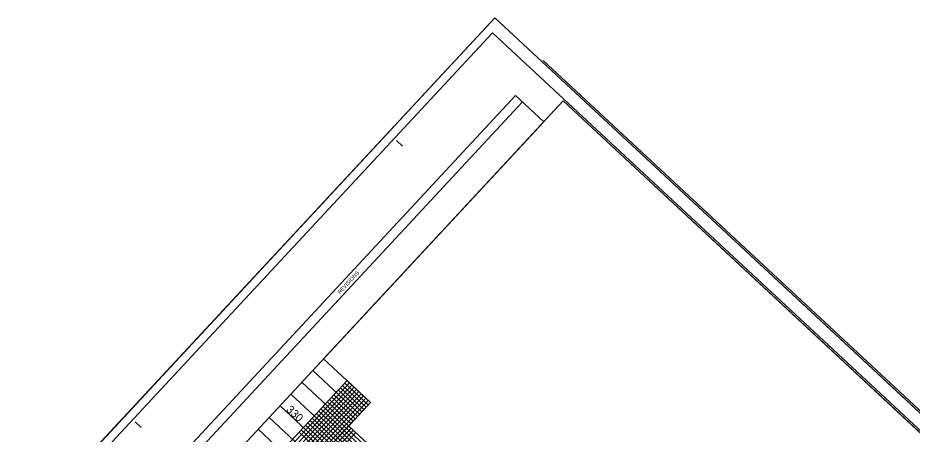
# Model space of a CAD drawing. Extents: x 2057696 to 2061410, y 685900 to 689434.
# Drawn here: x 2057696 to 2058814, y 688913 to 689434 of the extents above; entities that cross this region are included whole.
import ezdxf

# ---------------------------------------------------------------- set-up
doc = ezdxf.new("R2010")
doc.units = 0
for name, color, linetype in [('Default', 7, 'Continuous'), ('Exist Vertical Profile Vertical Axis Label', 7, 'Continuous'), ('Prop Boundary Buffer Zone 2', 7, 'Continuous'), ('Prop Vertical Profile Curve Label', 7, 'Continuous'), ('Sheet Cutting Line CELL', 7, 'Continuous'), ('Sheet Plan CELL', 7, 'Continuous'), ('Sheet Plot Border Inside CELL', 7, 'Continuous')]:
    doc.layers.add(name, color=color, linetype=linetype)

msp = doc.modelspace()

# ---------------------------------------------------------------- linework, layer by layer
at = {"layer": 'Default'}
for p, q in [((2058292.7, 689433.5), (2057696.3, 688791.9)), ((2059279.2, 688516.6), (2058292.7, 689433.5)), ((2059279, 688519.5), (2058353.1, 689380.2)), ((2057806.1, 688714.4), (2058378, 689329.7)), ((2057896.3, 688865.4), (2058326.9, 689328.7)), ((2059257, 688512.7), (2058378, 689329.7)), ((2058169.8, 689280.2), (2058177.1, 689273.4)), ((2058107.8, 688980.2), (2057849.1, 688701.8)), ((2058122.4, 688966.5), (2057863.7, 688688.2)), ((2058122.4, 688966.5), (2058137.1, 688952.9)), ((2057843, 688928.6), (2057850.4, 688921.8)), ((2058109.8, 688923.6), (2057878.4, 688674.6))]:
    msp.add_line(p, q, dxfattribs=at)
for points in [[(2057696.3, 688791.9), (2058682.8, 687875), (2059279.2, 688516.6), (2058292.7, 689433.5)], [(2057714.8, 688796.5), (2058691.1, 687889.2), (2059265.7, 688507.4), (2058289.4, 689414.7)], [(2057887.8, 688873.4), (2058318.4, 689336.7), (2058353.9, 689303.7), (2057923.2, 688840.4)]]:
    msp.add_lwpolyline(points, close=True, dxfattribs=at)
at = {"layer": 'Exist Vertical Profile Vertical Axis Label'}
for points in [[(2057852, 688699.1), (2058110.7, 688977.4), (2058113.6, 688974.7), (2057854.9, 688696.4)], [(2057857.9, 688693.6), (2058116.6, 688972), (2058119.5, 688969.3), (2057860.8, 688690.9)], [(2057866.6, 688685.5), (2058125.3, 688963.8), (2058128.3, 688961.1), (2057869.6, 688682.8)], [(2057872.5, 688680), (2058131.2, 688958.4), (2058134.1, 688955.6), (2057875.4, 688677.3)], [(2057881.3, 688671.9), (2058112.8, 688920.9)], [(2058115.7, 688918.2), (2057884.2, 688669.1)], [(2057887.2, 688666.4), (2058118.6, 688915.5)]]:
    msp.add_lwpolyline(points, dxfattribs=at)
at = {"layer": 'Prop Boundary Buffer Zone 2'}
for p, q in [((2058123.5, 688938.3), (2058064.9, 688992.7)), ((2057849.1, 688701.8), (2058107.8, 688980.2)), ((2058107.8, 688980.2), (2058137.1, 688952.9)), ((2057863.7, 688688.2), (2058122.4, 688966.5)), ((2058860.5, 688198.6), (2058037.6, 688963.4)), ((2058137.1, 688952.9), (2057878.4, 688674.6)), ((2058833.2, 688169.3), (2058010.4, 688934.1))]:
    msp.add_line(p, q, dxfattribs=at)
at = {"layer": 'Prop Vertical Profile Curve Label'}
for points in [[(2058210.3, 688884.8), (2058901.3, 688242.6), (2059147.2, 688507.2), (2059089, 688561.3), (2059142.6, 688619), (2058378, 689329.7), (2058078.5, 689007.4), (2058137.1, 688952.9)], [(2058137.1, 688952.9), (2058107.8, 688980.2), (2057849.1, 688701.8), (2058611.6, 687993), (2058870.3, 688271.4), (2058210.3, 688884.8)], [(2058210.3, 688884.8), (2058183.1, 688855.5), (2058109.8, 688923.6), (2058137.1, 688952.9)], [(2058137.1, 688952.9), (2058109.8, 688923.6), (2058183.1, 688855.5), (2058210.3, 688884.8)]]:
    msp.add_lwpolyline(points, dxfattribs=at)
at = {"layer": 'Sheet Cutting Line CELL'}
for p, q in [((2058137.1, 688952.9), (2058078.5, 689007.4)), ((2057849.1, 688701.8), (2058107.8, 688980.2)), ((2058109.8, 688923.6), (2058051.2, 688978.1)), ((2058846.8, 688184), (2058024, 688948.8)), ((2058874.1, 688213.3), (2058109.8, 688923.6)), ((2058819.6, 688154.7), (2057996.8, 688919.5))]:
    msp.add_line(p, q, dxfattribs=at)
at = {"layer": 'Sheet Plot Border Inside CELL'}
for p, q in [((2058134.3, 688950), (2058105, 688977.2)), ((2058126.2, 688941.2), (2058096.9, 688968.4)), ((2058128.9, 688944.1), (2058099.6, 688971.4)), ((2058131.6, 688947.1), (2058102.3, 688974.3)), ((2058115.3, 688929.5), (2058086, 688956.7)), ((2058118, 688932.4), (2058088.7, 688959.6)), ((2058120.7, 688935.3), (2058091.4, 688962.6)), ((2058837.6, 688236.2), (2058075.1, 688945)), ((2058840.4, 688239.2), (2058077.8, 688947.9)), ((2058112.6, 688926.6), (2058083.3, 688953.8)), ((2058826.7, 688224.5), (2058064.2, 688933.3)), ((2058832.2, 688230.4), (2058069.6, 688939.1)), ((2058834.9, 688233.3), (2058072.4, 688942.1)), ((2058818.6, 688215.7), (2058056, 688924.5)), ((2058821.3, 688218.6), (2058058.8, 688927.4)), ((2058824, 688221.6), (2058061.5, 688930.3)), ((2058810.4, 688206.9), (2058047.9, 688915.7)), ((2058813.1, 688209.9), (2058050.6, 688918.6))]:
    msp.add_line(p, q, dxfattribs=at)

# ---------------------------------------------------------------- texts
at = {"layer": 'Default'}
msp.add_text('REVISIONS', height=4.8, rotation=47.0934, dxfattribs=at).set_placement((2058098.8, 689088.1))
at = {"layer": 'Sheet Plan CELL'}
msp.add_text('330', height=10, rotation=317.0934, dxfattribs=at).set_placement((2058031, 688943))

doc.saveas('drawing.dxf')
